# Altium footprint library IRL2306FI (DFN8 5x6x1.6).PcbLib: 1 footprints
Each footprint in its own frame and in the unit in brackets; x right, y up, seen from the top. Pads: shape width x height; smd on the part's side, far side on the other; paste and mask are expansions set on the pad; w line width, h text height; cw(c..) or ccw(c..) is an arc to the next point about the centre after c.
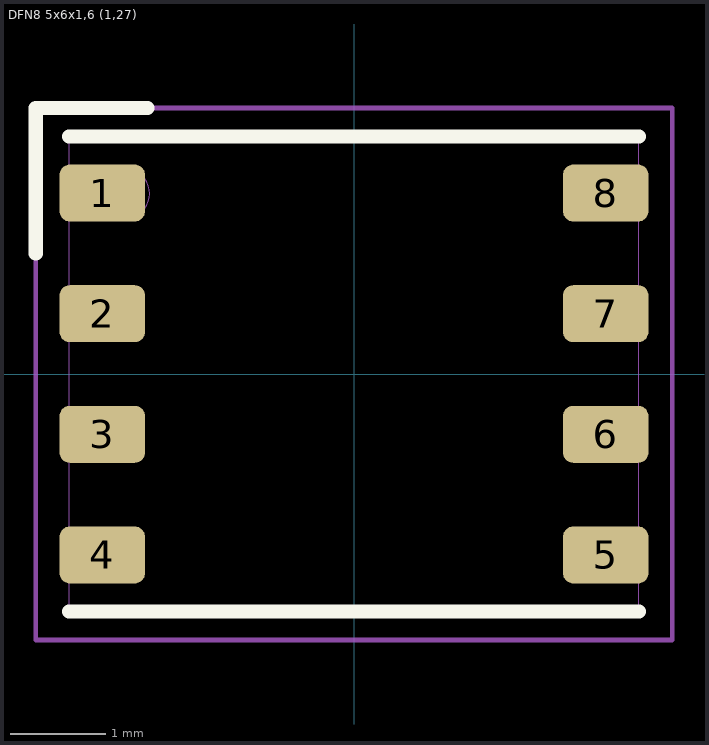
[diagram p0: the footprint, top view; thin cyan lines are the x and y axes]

## DFN8 5x6x1,6 (1,27) [mm]
height 1.7
pads (8):
  rrect35% 0.9x0.6 smd mask+0.05: 1(-2.65,1.905) 2(-2.65,0.635) 3(-2.65,-0.635) 4(-2.65,-1.905) 5(2.65,-1.905) 6(2.65,-0.635) 7(2.65,0.635) 8(2.65,1.905)
Top Overlay:
  lines w0.15: -3.35,1.27 -3.35,2.8 -2.175,2.8 ; -3,-2.5 3,-2.5 ; -3,2.5 3,2.5
Top Assembly:
  circle w0: c-2.4,1.9 r0.25
  lines w0: -3,-2.5 -3,2.5 3,2.5 3,-2.5 -3,-2.5
  text ".Designator" at -2.618,-0.355 h1.52
Top Courtyard:
  lines w0.05: -3.35,-2.8 -3.35,2.8 3.35,2.8 3.35,-2.8 -3.35,-2.8
3D body "DFN8 5x6x1,6 (1,27).STEP": height 1.6, standoff 0, extent -3,-2.499 3,2.499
